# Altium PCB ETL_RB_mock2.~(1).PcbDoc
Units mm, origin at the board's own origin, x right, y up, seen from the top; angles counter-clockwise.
Board outline 130.3 x 56.5 mm, 2 copper layers (Top Layer, Bottom Layer), stack 0.137 mm thick; 6 components, 186 nets, 264 pads, 0 vias.
Unrouted connection lines stored in the file: 395.
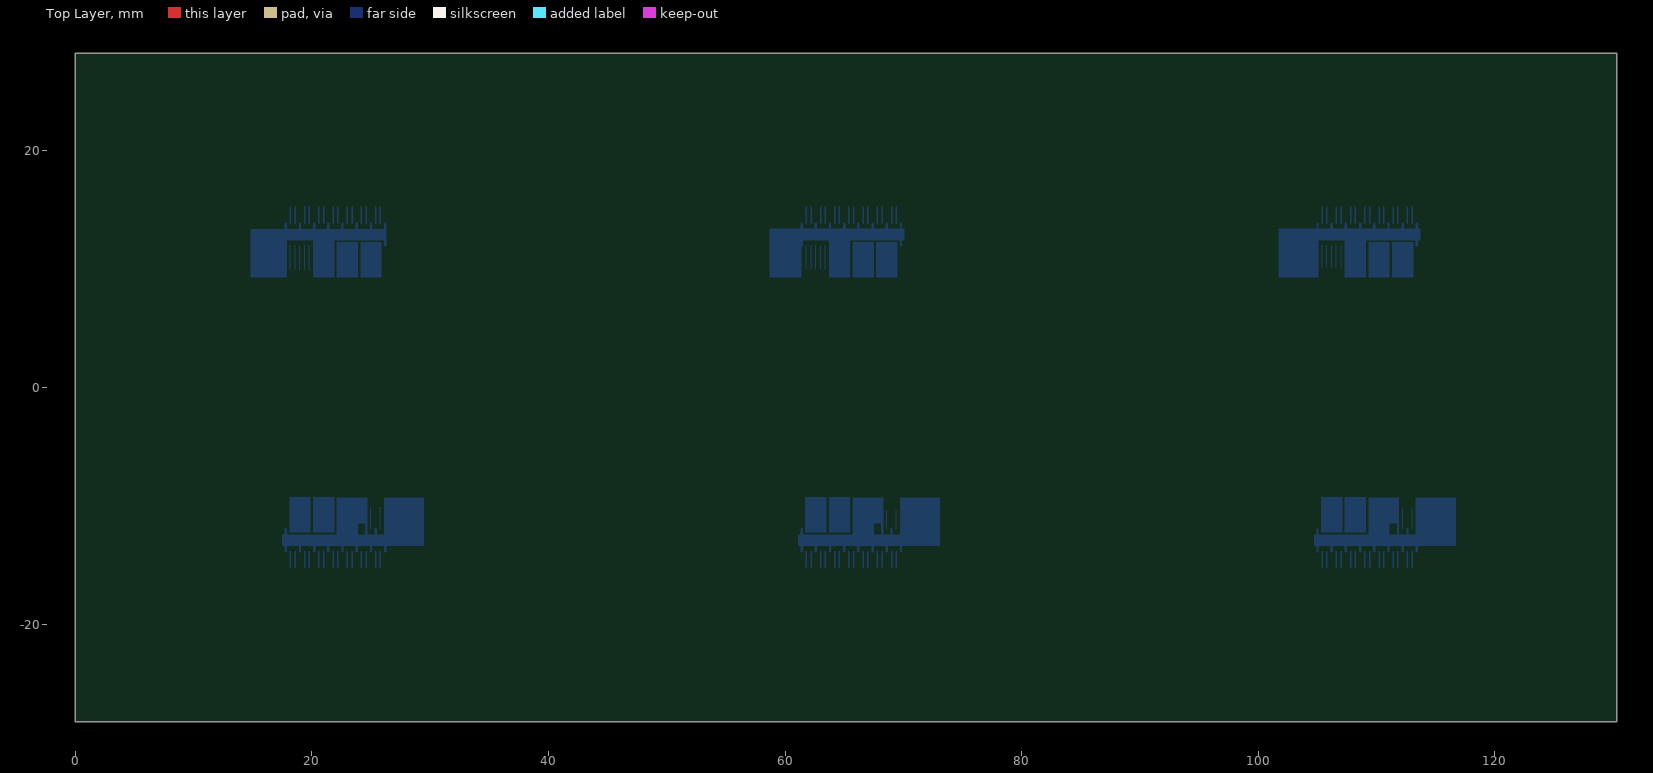
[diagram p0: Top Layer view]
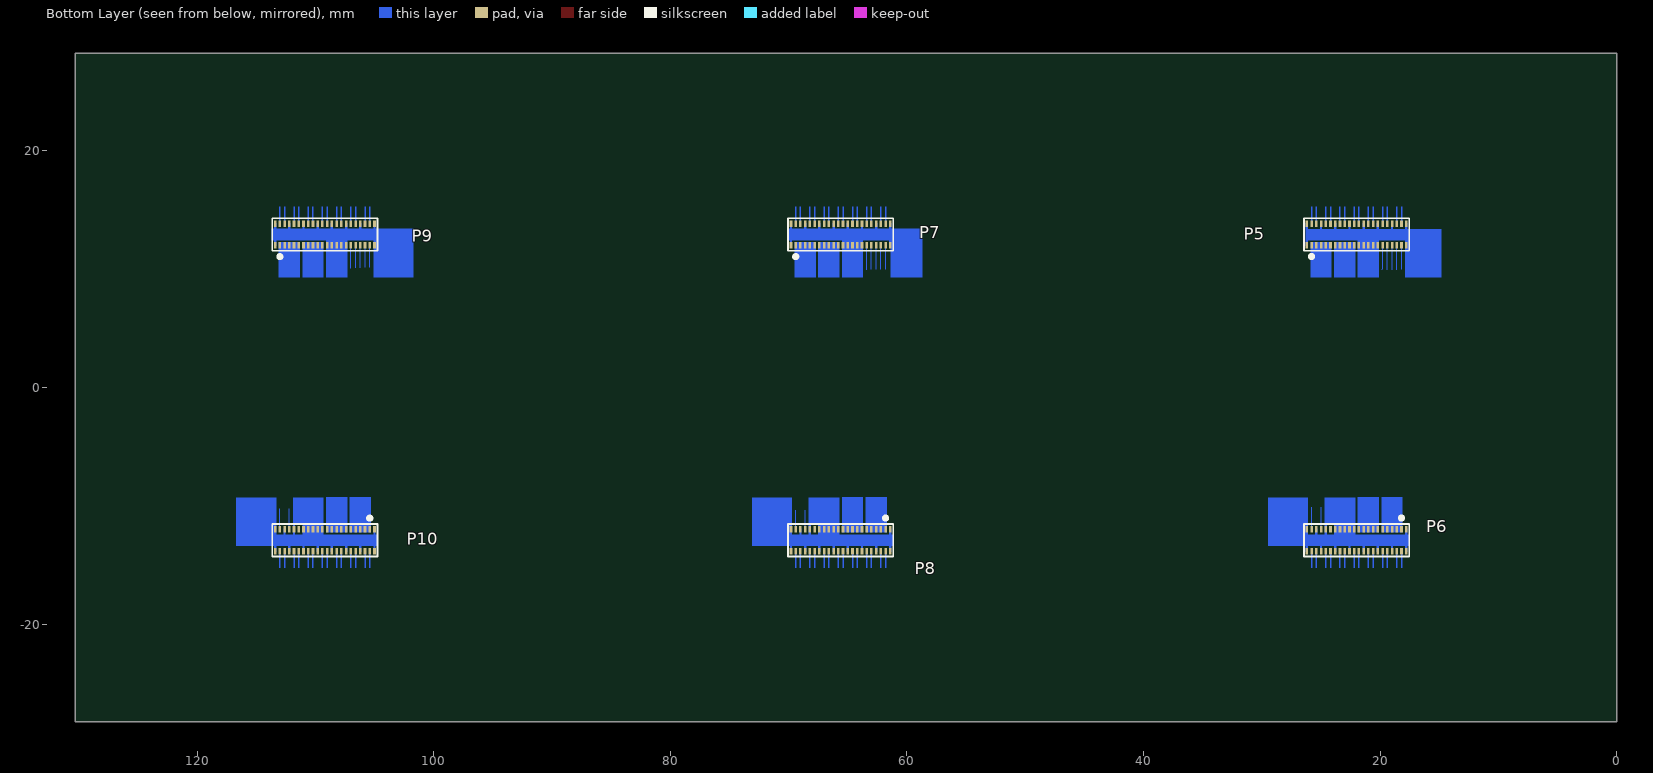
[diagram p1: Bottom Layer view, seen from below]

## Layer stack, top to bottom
Top Solder: solder mask 0.0178, Solder Resist, Dk 4.1
Top Layer: signal copper 0.0175
Dielectric 4: core 0.1016, TU-863, Dk 3.7
Bottom Layer: signal copper 0.0175
Bottom Solder: solder mask 0.0178, Solder Resist, Dk 4.1

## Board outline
0,-28.25 130.3,-28.25 130.3,28.25 0,28.25

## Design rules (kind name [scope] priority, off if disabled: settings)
Clearance [All] p1: gap=0.076 ignorepadtopadclearanceinfootprint=FALSE except(0: Arc-Hole Track-Hole SMDPad-Hole THPad-Hole Via-Hole Fill-Hole Poly-Hole Region-Hole Text-Hole)
Height [All] p1 off: minheight=0 maxheight=25.4 prefheight=12.7
HoleToHoleClearance HoleToHoleClearance_1 [InNet('GND') or InNet('LV_RB') or InNet('1V5A') or InNet('1V5D') or InNet('1V2A') or InNet('1V2B') or InNet('1V2C') or InNet('1V2D') vs InNet('GND') or InNet('LV_RB') or InNet('1V5A') or InNet('1V5D') or InNet('1V2A') or InNet('1V2B') or InNet('1V2C') or InNet('1V2D')] p1: gap=0.15 allowstackedmicrovias=TRUE
HoleToHoleClearance [All] p2: gap=0.254 allowstackedmicrovias=TRUE
MinimumSolderMaskSliver [All] p1: minsoldermaskwidth=0.102
PlaneClearance PlaneClearance_1 [InNetClass('BV')] p1: clearance=0.508
PlaneClearance [All] p2: clearance=0.152
PlaneConnect PlaneConnect_1 [All] p1: planeconnectstyle=Direct reliefexpansion=0.508 reliefentries=4 reliefconductorwidth=0.254 reliefairgap=0.254
PolygonConnect [All] p1: connectstyle=Relief reliefconductorwidth=0.254 reliefentries=4 polygonreliefangle="90 Angle" airgapwidth=0.254
RoomDefinition WP7B [InComponentClass('WP7B')] p1 off: confinementstyle=ConfineIn formatcopy=TRUE lockcomponents=FALSE outline 192.75,16.8 613.75,16.8 613.75,46.8 192.75,46.8
RoomDefinition lpGBT [InComponentClass('lpGBT')] p2 off: confinementstyle=ConfineIn formatcopy=TRUE lockcomponents=FALSE outline 192,-36.75 1047,-36.75 1047,-1.75 192,-1.75
RoutingVias [All] p1: holewidth=0.25 width=0.4 viastyle="Through Hole" minholewidth=0.15 minwidth=0.25 maxholewidth=0.711 maxwidth=1.27
SilkToSilkClearance [All] p1: silktosilkclearance=0.025
SilkToSolderMaskClearance [IsPad] p1: minsilkscreentomaskgap=0.025 clearancetoexposedcopper=TRUE
SolderMaskExpansion SolderMaskExpansion_1 [InPadClass('WP7B40PAD')] p1: expansion=0.038 istentingtop=FALSE
SolderMaskExpansion [All] p2: expansion=0.051 istentingtop=FALSE
Width Width_HS [InNetClass('HS')] p1: maxlimit=0.13 minlimit=0.076 preferedwidth=0.12 bottomlayer_minwidth=0.12 bottomlayer_maxwidth=0.12 minimp=50.000000 maximp=50.000000 favimp=50.000000 // impedance controlled signals
Width [All] p2: maxlimit=2.54 minlimit=0.076 preferedwidth=0.12 toplayer_minwidth=0.076 minimp=50.000000 maximp=50.000000 favimp=50.000000
23 further rules are at their usual default settings.

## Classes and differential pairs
pad class WP7B40PAD: P5-1 P5-2 P5-3 P5-4 P5-5 P5-6 P5-7 P5-8 P5-9 P5-10 P5-11 P5-12 P5-13 P5-14 P5-15 P5-16 P5-17 P5-18 P5-19 P5-20 P5-21 P5-22 P5-23 P5-24 P5-25 P5-26 P5-27 P5-28 P5-29 P5-30 P5-31 P5-32 P5-33 P5-34 P5-35 P5-36 P5-37 P5-38 P5-39 P5-40 P5-41 P5-42 P5-43 P5-44 P6-1 P6-2 P6-3 P6-4 P6-5 P6-6 P6-7 P6-8 P6-9 P6-10 P6-11 P6-12 P6-13 P6-14 P6-15 P6-16 P6-17 P6-18 P6-19 P6-20 P6-21 P6-22 P6-23 P6-24 P6-25 P6-26 P6-27 P6-28 P6-29 P6-30 P6-31 P6-32 P6-33 P6-34 P6-35 P6-36 P6-37 P6-38 P6-39 P6-40 P6-41 P6-42 P6-43 P6-44 P7-1 P7-2 P7-3 P7-4 P7-5 P7-6 P7-7 P7-8 P7-9 P7-10 P7-11 P7-12 P7-13 P7-14 P7-15 P7-16 P7-17 P7-18 P7-19 P7-20 P7-21 P7-22 P7-23 P7-24 P7-25 P7-26 P7-27 P7-28 P7-29 P7-30 P7-31 P7-32 P7-33 P7-34 P7-35 P7-36 P7-37 P7-38 P7-39 P7-40 P7-41 P7-42 P7-43 P7-44 P8-1 P8-2 P8-3 P8-4 P8-5 P8-6 P8-7 P8-8 P8-9 P8-10 P8-11 P8-12 P8-13 P8-14 P8-15 P8-16 P8-17 P8-18 P8-19 P8-20 P8-21 P8-22 P8-23 P8-24 P8-25 P8-26 P8-27 P8-28 P8-29 P8-30 P8-31 P8-32 P8-33 P8-34 P8-35 P8-36 P8-37 P8-38 P8-39 P8-40 P8-41 P8-42 P8-43 P8-44 P9-1 P9-2 P9-3 P9-4 P9-5 P9-6 P9-7 P9-8 P9-9 P9-10 P9-11 P9-12 P9-13 P9-14 P9-15 P9-16 P9-17 P9-18 P9-19 P9-20 P9-21 P9-22 P9-23 P9-24 P9-25 P9-26 P9-27 P9-28 P9-29 P9-30 P9-31 P9-32 P9-33 P9-34 P9-35 P9-36 P9-37 P9-38 P9-39 P9-40 P9-41 P9-42 P9-43 P9-44 P10-1 P10-2 P10-3 P10-4 P10-5 P10-6 P10-7 P10-8 P10-9 P10-10 P10-11 P10-12 P10-13 P10-14 P10-15 P10-16 P10-17 P10-18 P10-19 P10-20 P10-21 P10-22 P10-23 P10-24 P10-25 P10-26 P10-27 P10-28 P10-29 P10-30 P10-31 P10-32 P10-33 P10-34 P10-35 P10-36 P10-37 P10-38 P10-39 P10-40 P10-41 P10-42 P10-43 P10-44

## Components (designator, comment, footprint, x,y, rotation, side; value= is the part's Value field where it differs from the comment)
P5 "WP7B-P040VA1" WP7B-40P 25.8,12 r180 bottom locked
P6 "WP7B-P040VA1" WP7B-40P 18.2,-12 r0 bottom locked
P7 "WP7B-P040VA1" WP7B-40P 69.4,12 r180 bottom locked
P8 "WP7B-P040VA1" WP7B-40P 61.8,-12 r0 bottom locked
P9 "WP7B-P040VA1" WP7B-40P 113,12 r180 bottom locked
P10 "WP7B-P040VA1" WP7B-40P 105.4,-12 r0 bottom locked

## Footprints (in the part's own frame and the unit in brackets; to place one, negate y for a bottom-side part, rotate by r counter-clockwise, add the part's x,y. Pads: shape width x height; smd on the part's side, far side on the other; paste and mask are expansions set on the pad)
WP7B-40P [mm]
  rect 0.22x0.55 smd: 1(0,0) 2(0.4,0) 3(0.8,0) 4(1.2,0) 5(1.6,0) 6(2,0) 7(2.4,0) 8(2.8,0) 9(3.2,0) 10(3.6,0) 11(4,0) 12(4.4,0) 13(4.8,0) 14(5.2,0) 15(5.6,0) 16(6,0) 17(6.4,0) 18(6.8,0) 19(7.2,0) 20(7.6,0) 21(7.6,1.85) 22(7.2,1.85) 23(6.8,1.85) 24(6.4,1.85) 25(6,1.85) 26(5.6,1.85) 27(5.2,1.85) 28(4.8,1.85) 29(4.4,1.85) 30(4,1.85) 31(3.6,1.85) 32(3.2,1.85) 33(2.8,1.85) 34(2.4,1.85) 35(2,1.85) 36(1.6,1.85) 37(1.2,1.85) 38(0.8,1.85) 39(0.4,1.85) 40(0,1.85) 41(-0.4,0) 42(8,0) 43(8,1.85) 44(-0.4,1.85)
  silkscreen extent -0.65,-1 8.25,2.3, body extent -1.5,-0.32 9.1,2.17, height 0.5

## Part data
P5 P6 P7 P8 P9 P10: library part WP7B-40P, "plug"

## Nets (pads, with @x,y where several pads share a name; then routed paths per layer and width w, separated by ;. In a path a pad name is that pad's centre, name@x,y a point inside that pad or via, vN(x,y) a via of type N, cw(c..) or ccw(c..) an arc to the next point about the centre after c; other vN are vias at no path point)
1V0A: P5.20 P7.20 P9.20 | length 5.8
  Bottom Layer w0.102: 18.2,10 P5.20 ; 61.8,10 P7.20 ; 105.4,10.15 P9.20
1V2_mon0: P5.17 | length 2
  Bottom Layer w0.102: 19.4,9.95 P5.17
1V2_mon1: P5.18 | length 2
  Bottom Layer w0.102: 19,9.95 P5.18
1V2_mon2: P7.17 | length 2
  Bottom Layer w0.102: 63,10 P7.17
1V2_mon3: P7.18 | length 2
  Bottom Layer w0.102: 62.6,10 P7.18
1V2_mon4: P9.17 | length 1.9
  Bottom Layer w0.102: 106.6,10.1 P9.17
1V2_mon5: P9.18 | length 1.9
  Bottom Layer w0.102: 106.2,10.1 P9.18
1V2_RB: 
1V2A: P5.1 P5.2 P5.3 P5.4 P5.5 P5.6 P5.7 P5.8 P5.9 P5.10 P6.6 P6.7 P6.8 P6.9 P6.10
1V2B: P6.1 P6.2 P6.3 P6.4 P6.5 P8.1 P8.2 P8.3 P8.4 P8.5 P8.6 P8.7 P8.8 P8.9 P8.10
1V2C: P7.1 P7.2 P7.3 P7.4 P7.5 P7.6 P7.7 P7.8 P7.9 P7.10 P9.1 P9.2 P9.3 P9.4 P9.5
1V2D: P9.6 P9.7 P9.8 P9.9 P9.10 P10.1 P10.2 P10.3 P10.4 P10.5 P10.6 P10.7 P10.8 P10.9 P10.10
1V5A: 
1V5D: 
2V5F: 
2V5RX: 
2V5TX: 
ADC1: 
ADC2: 
ADC3: 
ADC4: 
ADC6: 
ADC7: 
ADC_IN18: 
ADC_IN21: 
ADC_IN22: 
ADC_IN23: 
ADC_IN24: 
ADC_IN25: 
ADC_IN28: 
ADC_IN29: 
ADC_IN30: 
AGND0: P5.19 | length 2
  Bottom Layer w0.102: 18.6,9.95 P5.19
AGND1: P7.19 | length 2
  Bottom Layer w0.102: 62.2,10 P7.19
AGND2: P9.19 | length 1.8
  Bottom Layer w0.102: 105.8,10.15 P9.19
BV0: 
BV1: 
BV2: 
ECLK0N: P6.27 | length 1.4
  Bottom Layer w0.12: 23.4,-15.25 P6.27
ECLK0P: P6.28 | length 1.4
  Bottom Layer w0.12: 23,-15.25 P6.28
ECLK1N: P6.39 | length 1.4
  Bottom Layer w0.12: 18.6,-15.25 P6.39
ECLK1P: P6.40 | length 1.4
  Bottom Layer w0.12: 18.2,-15.25 P6.40
ECLK2N: P8.39 | length 1.4
  Bottom Layer w0.12: 62.2,-15.25 P8.39
ECLK2P: P8.40 | length 1.4
  Bottom Layer w0.12: 61.8,-15.25 P8.40
ECLK3N: P8.28 | length 1.4
  Bottom Layer w0.12: 66.6,-15.25 P8.28
ECLK3P: P8.27 | length 1.4
  Bottom Layer w0.12: 67,-15.25 P8.27
ECLK4N: P10.40 | length 1.4
  Bottom Layer w0.12: 105.4,-15.25 P10.40
ECLK4P: P10.39 | length 1.4
  Bottom Layer w0.12: 105.8,-15.25 P10.39
ECLK5N: P10.28 | length 1.4
  Bottom Layer w0.12: 110.2,-15.25 P10.28
ECLK5P: P10.27 | length 1.4
  Bottom Layer w0.12: 110.6,-15.25 P10.27
ECLK22N: P9.28 | length 1.4
  Bottom Layer w0.12: P9.28 108.2,15.25
ECLK22P: P9.27 | length 1.4
  Bottom Layer w0.12: P9.27 107.8,15.25
ECLK23N: P7.40 | length 1.4
  Bottom Layer w0.12: P7.40 69.4,15.25
ECLK23P: P7.39 | length 1.4
  Bottom Layer w0.12: P7.39 69,15.25
ECLK24N: P9.39 | length 1.4
  Bottom Layer w0.12: P9.39 112.6,15.25
ECLK24P: P9.40 | length 1.4
  Bottom Layer w0.12: P9.40 113,15.25
ECLK25N: P7.28 | length 1.4
  Bottom Layer w0.12: P7.28 64.6,15.25
ECLK25P: P7.27 | length 1.4
  Bottom Layer w0.12: P7.27 64.2,15.25
ECLK26N: P5.40 | length 1.4
  Bottom Layer w0.12: P5.40 25.8,15.25
ECLK26P: P5.39 | length 1.4
  Bottom Layer w0.12: P5.39 25.4,15.25
ECLK27N: P5.28 | length 1.4
  Bottom Layer w0.12: P5.28 21,15.25
ECLK27P: P5.27 | length 1.4
  Bottom Layer w0.12: P5.27 20.6,15.25
EDIN00N: P6.34 | length 1.4
  Bottom Layer w0.12: 20.6,-15.25 P6.34
EDIN00P: P6.33 | length 1.4
  Bottom Layer w0.12: 21,-15.25 P6.33
EDIN02N: P6.25 | length 1.4
  Bottom Layer w0.12: 24.2,-15.25 P6.25
EDIN02P: P6.24 | length 1.4
  Bottom Layer w0.12: 24.6,-15.25 P6.24
EDIN10N: P8.34 | length 1.4
  Bottom Layer w0.12: 64.2,-15.25 P8.34
EDIN10P: P8.33 | length 1.4
  Bottom Layer w0.12: 64.6,-15.25 P8.33
EDIN12N: P8.24 | length 1.4
  Bottom Layer w0.12: 68.2,-15.25 P8.24
EDIN12P: P8.25 | length 1.4
  Bottom Layer w0.12: 67.8,-15.25 P8.25
EDIN20N: P10.34 | length 1.4
  Bottom Layer w0.12: 107.8,-15.25 P10.34
EDIN20P: P10.33 | length 1.4
  Bottom Layer w0.12: 108.2,-15.25 P10.33
EDIN22N: P10.25 | length 1.4
  Bottom Layer w0.12: 111.4,-15.25 P10.25
EDIN22P: P10.24 | length 1.4
  Bottom Layer w0.12: 111.8,-15.25 P10.24
EDIN30N: P9.34 | length 1.4
  Bottom Layer w0.12: P9.34 110.6,15.25
EDIN30P: P9.33 | length 1.4
  Bottom Layer w0.12: P9.33 110.2,15.25
EDIN32N: P9.25 | length 1.4
  Bottom Layer w0.12: P9.25 107,15.25
EDIN32P: P9.24 | length 1.4
  Bottom Layer w0.12: P9.24 106.6,15.25
EDIN40N: P7.34 | length 1.4
  Bottom Layer w0.12: P7.34 67,15.25
EDIN40P: P7.33 | length 1.4
  Bottom Layer w0.12: P7.33 66.6,15.25
EDIN42N: P7.25 | length 1.4
  Bottom Layer w0.12: P7.25 63.4,15.25
EDIN42P: P7.24 | length 1.4
  Bottom Layer w0.12: P7.24 63,15.25
EDIN50N: P5.34 | length 1.4
  Bottom Layer w0.12: P5.34 23.4,15.25
EDIN50P: P5.33 | length 1.4
  Bottom Layer w0.12: P5.33 23,15.25
EDIN52N: P5.25 | length 1.4
  Bottom Layer w0.12: P5.25 19.8,15.25
EDIN52P: P5.24 | length 1.4
  Bottom Layer w0.12: P5.24 19.4,15.25
EDOUT00N: P6.36 | length 1.4
  Bottom Layer w0.12: 19.8,-15.25 P6.36
EDOUT00P: P6.37 | length 1.4
  Bottom Layer w0.12: 19.4,-15.25 P6.37
EDOUT02N: P8.37 | length 1.4
  Bottom Layer w0.12: 63,-15.25 P8.37
EDOUT02P: P8.36 | length 1.4
  Bottom Layer w0.12: 63.4,-15.25 P8.36
EDOUT10N: P10.37 | length 1.4
  Bottom Layer w0.12: 106.6,-15.25 P10.37
EDOUT10P: P10.36 | length 1.4
  Bottom Layer w0.12: 107,-15.25 P10.36
EDOUT20N: P9.37 | length 1.4
  Bottom Layer w0.12: P9.37 111.8,15.25
EDOUT20P: P9.36 | length 1.4
  Bottom Layer w0.12: P9.36 111.4,15.25
EDOUT22N: P7.37 | length 1.4
  Bottom Layer w0.12: P7.37 68.2,15.25
EDOUT22P: P7.36 | length 1.4
  Bottom Layer w0.12: P7.36 67.8,15.25
EDOUT30N: P5.37 | length 1.4
  Bottom Layer w0.12: P5.37 24.6,15.25
EDOUT30P: P5.36 | length 1.4
  Bottom Layer w0.12: P5.36 24.2,15.25
GBT_RESET_B: 
GND: P5.11 P5.12 P5.13 P5.14 P5.15 P5.23 P5.26 P5.29 P5.32 P5.35 P5.38 P5.41 P5.42 P5.43 P5.44 P6.11 P6.12 P6.13 P6.14 P6.15 P6.17 P6.19 P6.23 P6.26 P6.29 P6.32 P6.35 P6.38 P6.41 P6.42 P6.43 P6.44 P7.11 P7.12 P7.13 P7.14 P7.15 P7.23 P7.26 P7.29 P7.32 P7.35 P7.38 P7.41 P7.42 P7.43 P7.44 P8.11 P8.12 P8.13 P8.14 P8.15 P8.17 P8.19 P8.23 P8.26 P8.29 P8.32 P8.35 P8.38 P8.41 P8.42 P8.43 P8.44 P9.11 P9.12 P9.13 P9.14 P9.15 P9.23 P9.26 P9.29 P9.32 P9.35 P9.38 P9.41 P9.42 P9.43 P9.44 P10.11 P10.12 P10.13 P10.14 P10.15 P10.17 P10.19 P10.23 P10.26 P10.29 P10.32 P10.35 P10.38 P10.41 P10.42 P10.43 P10.44 | length 61.2
  Bottom Layer w0.2: P6.44 P6.41 ; P5.42 P5.43 ; P6.38 19,-12.9 ; 19,13.1 P5.23 ; P6.35 20.2,-13 ; 20.2,12.9 P5.26 ; P6.32 21.4,-13 ; 21.4,12.9 P5.29 ; P6.29 22.6,-12.9 ; 22.6,13 P5.32 ; P6.26 23.8,-12.9 ; 23.8,13 P5.35 ; 24.6,-12.8 P6.17 24.6,-11.3 ; P6.23 25,-13.1 ; 25,12.9 P5.38 ; 25.4,-12.7 P6.19 ; P6.43 P6.42 ; P5.41 P5.44 ; P8.44 P8.41 ; P7.42 P7.43 ; P8.38 62.6,-12.9 ; 62.6,13.1 P7.23 ; P8.35 63.8,-13 ; 63.8,12.9 P7.26 ; P8.32 65,-13 ; 65,12.9 P7.29 ; P8.29 66.2,-12.9 ; 66.2,13 P7.32 ; P8.26 67.4,-12.9 ; 67.4,13 P7.35 ; 68.2,-12.7 P8.17 68.2,-11.3 ; P8.23 68.6,-13.1 ; 68.6,12.9 P7.38 ; 69,-12.9 P8.19 ; P8.43 P8.42 ; P7.41 P7.44 ; P10.44 P10.41 ; P9.42 P9.43 ; P10.38 106.2,-12.9 ; 106.2,13.1 P9.23 ; P10.35 107.4,-13 ; 107.4,12.9 P9.26 ; P10.32 108.6,-13 ; 108.6,12.9 P9.29 ; P10.29 109.8,-12.9 ; 109.8,13 P9.32 ; P10.26 111,-12.9 ; 111,13 P9.35 ; 111.8,-12.8 111.8,-11 ; P10.23 112.2,-13.1 ; 112.2,12.9 P9.38 ; 112.6,-12.9 P10.19 ; P10.43 P10.42 ; P9.41 P9.44
I_1V5: 
I_2V5RX: 
I_2V5TX: 
IC1_SCL: 
IC1_SDA: 
LD_DIS: 
LD_RSTN: 
LV_RB: 
M1SCL: P6.20 P8.20 P10.20 | length 5.2
  Bottom Layer w0.102: P6.20 25.8,-10.15 ; P8.20 69.4,-10.4 ; P10.20 113,-10.25
M1SDA: P6.18 P8.18 P10.18 | length 5.2
  Bottom Layer w0.102: P6.18 25,-10.15 ; P8.18 68.6,-10.4 ; P10.18 112.2,-10.25
M2SCL: 
M2SDA: 
NetC107_1: 
NetC108_1: 
NetC155_1: 
NetC169_1: 
NetD1_1: 
NetD1_2: 
NetIC1_A2: 
NetIC1_G1: 
NetIC1_H1: 
NetIC1_L1: 
NetIC1_M1: 
NetIC1_P2: 
NetIC1_P3: 
NetIC1_R16: 
NetIC1_R17: 
NetIC1_T16: 
NetIC1_T17: 
NetIC1_U16: 
NetIC1_U17: 
NetIC2_19: 
NetIC2_21: 
NetIC5_4: 
NetIC5_5: 
NetIC6_4: 
NetIC7_4: 
NetP4_1: 
NetP8_11: 
NetP16_1: 
NetP17_1: 
NetQ1_2: 
NetR222_2: 
NetR224_2: 
NetR226_2: 
ON0: 
ON1: 
ON2: 
ON3: 
PG0: 
PG1: 
PG2: 
PG3: 
READY0: 
REFCLKN: 
REFCLKP: 
RSSI: 
RSTB0: P5.16 | length 2.1
  Bottom Layer w0.102: P5.16 19.8,10 19.85,9.95
RSTB1: P7.16 | length 2
  Bottom Layer w0.102: 63.4,9.95 P7.16
RSTB2: P9.16 | length 1.9
  Bottom Layer w0.102: 107,10.05 P9.16
SC_I2C: 
T_EDIN00N: P6.22 | length 1.4
  Bottom Layer w0.12: 25.4,-15.25 P6.22
T_EDIN00P: P6.21 | length 1.4
  Bottom Layer w0.12: 25.8,-15.25 P6.21
T_EDIN02N: P6.31 | length 1.4
  Bottom Layer w0.12: 21.8,-15.25 P6.31
T_EDIN02P: P6.30 | length 1.4
  Bottom Layer w0.12: 22.2,-15.25 P6.30
T_EDIN10N: P8.22 | length 1.4
  Bottom Layer w0.12: 69,-15.25 P8.22
T_EDIN10P: P8.21 | length 1.4
  Bottom Layer w0.12: 69.4,-15.25 P8.21
T_EDIN12N: P8.31 | length 1.4
  Bottom Layer w0.12: 65.4,-15.25 P8.31
T_EDIN12P: P8.30 | length 1.4
  Bottom Layer w0.12: 65.8,-15.25 P8.30
T_EDIN20N: P10.22 | length 1.4
  Bottom Layer w0.12: 112.6,-15.25 P10.22
T_EDIN20P: P10.21 | length 1.4
  Bottom Layer w0.12: 113,-15.25 P10.21
T_EDIN22N: P10.31 | length 1.4
  Bottom Layer w0.12: 109,-15.25 P10.31
T_EDIN22P: P10.30 | length 1.4
  Bottom Layer w0.12: 109.4,-15.25 P10.30
T_EDIN30N: P9.21 | length 1.4
  Bottom Layer w0.12: P9.21 105.4,15.25
T_EDIN30P: P9.22 | length 1.4
  Bottom Layer w0.12: P9.22 105.8,15.25
T_EDIN32N: P9.30 | length 1.4
  Bottom Layer w0.12: P9.30 109,15.25
T_EDIN32P: P9.31 | length 1.4
  Bottom Layer w0.12: P9.31 109.4,15.25
T_EDIN40N: P7.22 | length 1.4
  Bottom Layer w0.12: P7.22 62.2,15.25
T_EDIN40P: P7.21 | length 1.4
  Bottom Layer w0.12: P7.21 61.8,15.25
T_EDIN42N: P7.31 | length 1.4
  Bottom Layer w0.12: P7.31 65.8,15.25
T_EDIN42P: P7.30 | length 1.4
  Bottom Layer w0.12: P7.30 65.4,15.25
T_EDIN50N: P5.22 | length 1.4
  Bottom Layer w0.12: P5.22 18.6,15.25
T_EDIN50P: P5.21 | length 1.4
  Bottom Layer w0.12: P5.21 18.2,15.25
T_EDIN52N: P5.31 | length 1.4
  Bottom Layer w0.12: P5.31 22.2,15.25
T_EDIN52P: P5.30 | length 1.4
  Bottom Layer w0.12: P5.30 21.8,15.25
Vref: 
pads on no net: P6.16 P8.16 P10.16

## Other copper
Bottom Layer:
  rectangle net GND: 109.3,-12.6 111.1,-11.4
  rectangle net GND: 58.7,12.425 70.1,13.425
  rectangle net GND: 14.8,9.3 17.9,12.7
  rectangle net GND: 58.7,9.3 61.4,12.6
  rectangle net GND: 63.7,9.3 65.5,12.6
  rectangle net GND: 107.3,9.3 109.1,12.6
  rectangle net GND: 101.7,9.3 105.1,13.425
  rectangle net GND: 101.7,12.425 113.7,13.425
  rectangle net GND: 20.1,9.3 21.9,12.6
  rectangle net GND: 22.1,-12.6 23.9,-11.4
  rectangle net GND: 22.1,-11.5 24.7,-9.3
  rectangle net GND: 109.3,-11.5 111.9,-9.3
  rectangle net GND: 113.3,-12.7 116.7,-9.3
  rectangle net GND: 67.4,-11.5 68.3,-9.3
  rectangle net GND: 65.7,-12.6 67.5,-9.3
  rectangle net GND: 69.7,-12.7 73.1,-9.3
  rectangle net GND: 26.1,-12.7 29.5,-9.3
  region net GND: 29.5,-12.425 17.5,-12.425 17.5,-13.425 29.5,-13.425
  region net GND: 73.1,-12.425 61.1,-12.425 61.1,-13.425 73.1,-13.425
  region net GND: 116.7,-12.425 104.7,-12.425 104.7,-13.425 116.7,-13.425
  rectangle net GND: 14.8,12.4 26.3,13.4
  rectangle net 1V2C: 67.7,9.275 69.5,12.275
  rectangle net 1V2C: 65.7,9.275 67.5,12.275
  rectangle net 1V2D: 109.3,9.275 111.1,12.275
  rectangle net 1V2C: 111.3,9.275 113.1,12.275
  region net 1V2D: 109.1,-9.275 107.3,-9.275 107.3,-12.275 109.1,-12.275
  region net 1V2D: 107.1,-9.275 105.3,-9.275 105.3,-12.275 107.1,-12.275
  region net 1V2B: 65.5,-9.275 63.7,-9.275 63.7,-12.275 65.5,-12.275
  region net 1V2B: 63.5,-9.275 61.7,-9.275 61.7,-12.275 63.5,-12.275
  region net 1V2B: 19.9,-9.275 18.1,-9.275 18.1,-12.275 19.9,-12.275
  region net 1V2A: 21.9,-9.275 20.1,-9.275 20.1,-12.275 21.9,-12.275
  rectangle net 1V2A: 22.1,9.275 23.9,12.275
  rectangle net 1V2A: 24.1,9.275 25.9,12.275

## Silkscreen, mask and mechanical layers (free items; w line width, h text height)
Mechanical 1:
  the board outline again, w0.15
Mechanical 14:
  lines w0.15: 5,28.25 38.35,28.25 ; 48.35,28.25 81.95,28.25 ; 125.3,28.25 0,28.25 ; 130.3,-28.2 130.3,23.25 ; 0,28.25 0,-28.25 130.3,-28.25 ; 0,28.25 0,28.25 ; 0,28.25 130.3,28.25 ; 130.3,-28.25 130.3,28.25 ; 130.3,-28.25 130.3,-28.25 ; 130.3,28.25 130.3,28.25

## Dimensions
130.3,-28.25 to 117.8,28.25 on Mechanical 14
0,28.25 to 130.3,7.4 on Mechanical 14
